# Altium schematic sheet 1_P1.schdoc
size 431 x 309 mm; Symbol: Sheet-Symbol_A4; Device: Sheet-Symbol_A4; @Page Name: P1; @Create Date: 2023-03-24; @Page Count: 1; @Page No: 1; @Project Name: weather_clock; @Schematic Name: Schematic1; @Update Date: 2023-03-27; Company: 嘉立创EDA; Page Size: A4; Version: V1.0
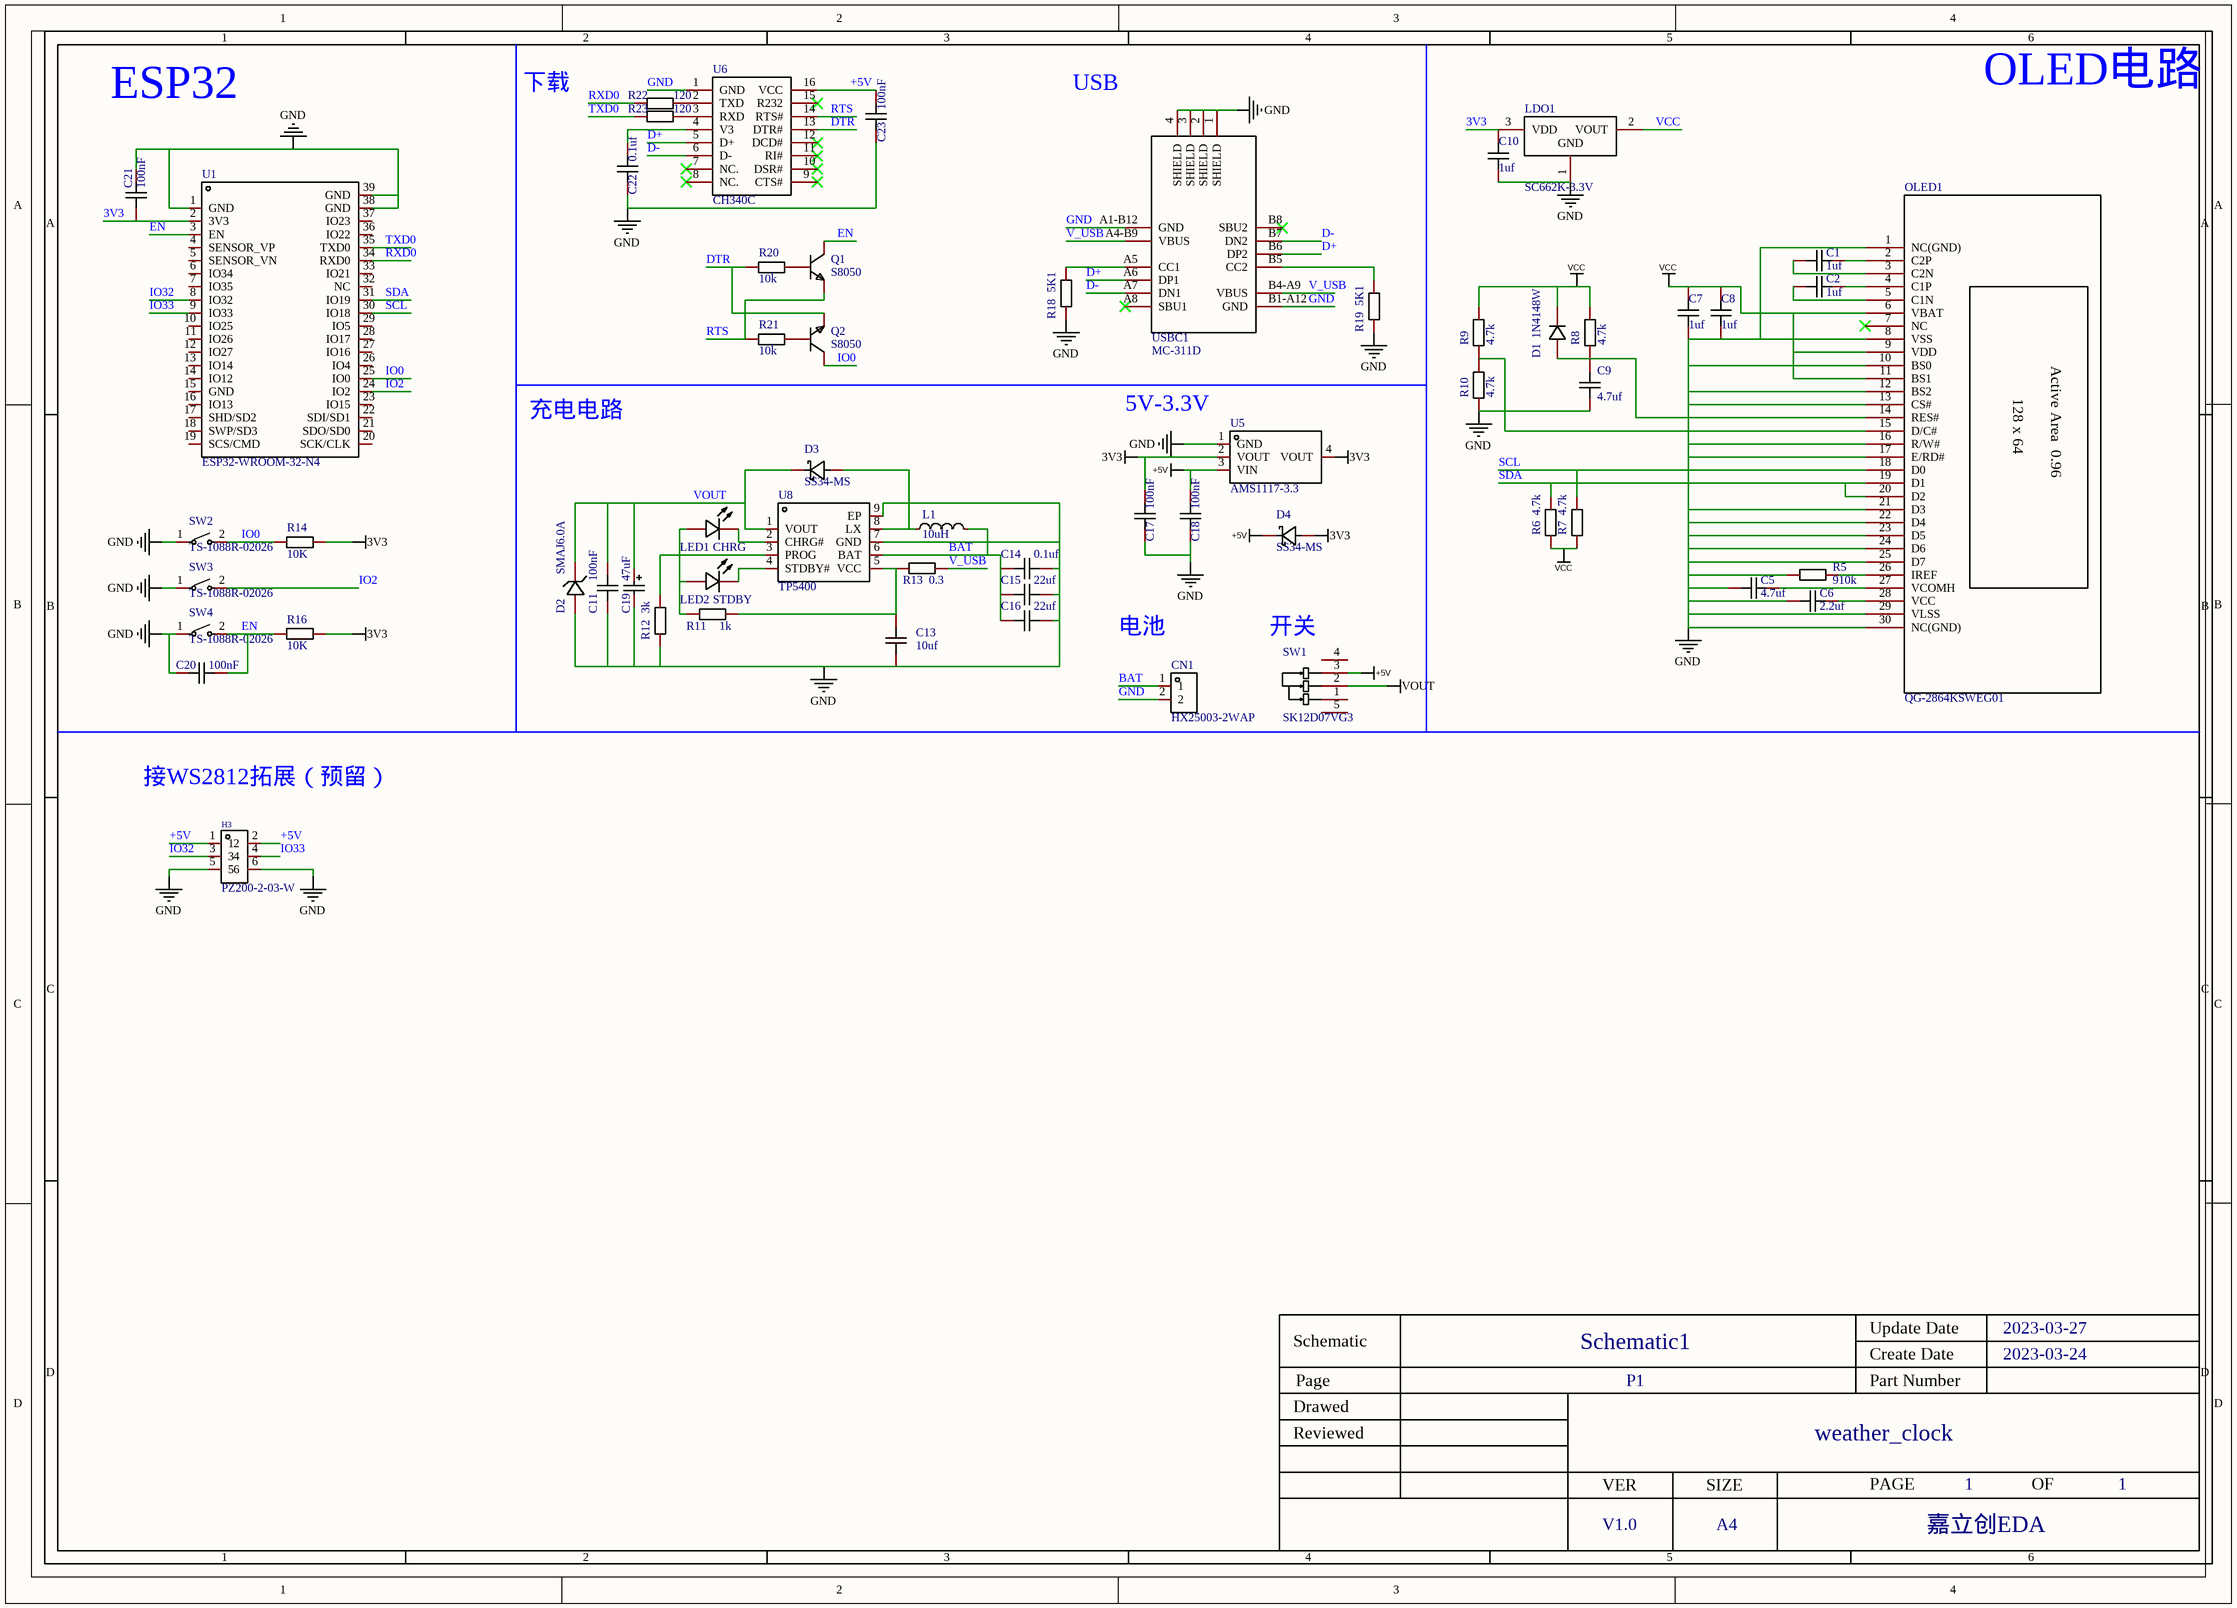
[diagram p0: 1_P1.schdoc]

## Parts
C1  1uf  [C0603]
C2  1uf  [C0603]
C5  4.7uf  [C0603]
C6  2.2uf  [C0603]
C7  1uf  [C0603]
C8  1uf  [C0603]
C9  4.7uf  [C0603]
C10  1uf  [C0603]
C11  100nF  [C0603]
C13  10uf  [C0603]
C14  0.1uf  [C0603]
C15  22uf  [C0603]
C16  22uf  [C0603]
C17  100nF  [C0603]
C18  100nF  [C0603]
C19  47uF  [CASE-A_3216]
C20  100nF  [C0603]
C21  100nF  [C0603]
C22  0.1uf  [C0603]
C23  100nF  [C0603]
CN1  HX25003-2WAP  [CONN-TH_2P-P2.50_HX25003-2WAP]
D1  1N4148W  [SOD-123_L2.8-W1.8-LS3.7-RD]
D2  SMAJ6.0A  [SMA_L4.3-W2.6-LS5.2-RD]
D3  SS34-MS  [DO-214AC_L4.3-W2.7-LS5.0-RD]
D4  SS34-MS  [DO-214AC_L4.3-W2.7-LS5.0-RD]
H3  PZ200-2-03-W  [HDR-TH_6P-P2.00-H-M-R2-C3-S2.00-W9.8]
L1  10uH  [IND-SMD_L4.5-W4.1_TMPA0402SP]
LDO1  SC662K-3.3V  [SOT-23-3_L2.9-W1.3-P1.90-LS2.4-BR]
LED1  CHRG  [LED0603-R-RD_GREEN]
LED2  STDBY  [LED0603-R-RD_GREEN]
OLED1  QG-2864KSWEG01  [OLED-SMD_QG-2864KSWEG01]
Q1  S8050  [SOT-23-3_L2.9-W1.6-P1.90-LS2.8-BR]
Q2  S8050  [SOT-23-3_L2.9-W1.6-P1.90-LS2.8-BR]
R5  910k  [R0603]
R6  4.7k  [R0603]
R7  4.7k  [R0603]
R8  4.7k  [R0603]
R9  4.7k  [R0603]
R10  4.7k  [R0603]
R11  1k  [R0603]
R12  3k  [R0603]
R13  0.3  [R0603]
R14  10K  [R0603]
R16  10K  [R0603]
R18  5K1  [R0603]
R19  5K1  [R0603]
R20  10k  [R0603]
R21  10k  [R0603]
R22  120  [R0603]
R23  120  [R0603]
SW1  SK12D07VG3  [SW-TH_SK12D07VG3]
SW2  TS-1088R-02026  [SW-SMD_L3.9-W3.0-P4.45]
SW3  TS-1088R-02026  [SW-SMD_L3.9-W3.0-P4.45]
SW4  TS-1088R-02026  [SW-SMD_L3.9-W3.0-P4.45]
U1  ESP32-WROOM-32-N4  [WIFIM-SMD_ESP32-WROOM-32-N4]
U5  AMS1117-3.3  [SOT-223-3_L6.5-W3.4-P2.30-LS7.0-BR]
U6  CH340C  [SOP-16_L10.0-W3.9-P1.27-LS6.0-BL]
U8  TP5400  [ESOP-8_L4.9-W3.9-P1.27-LS6.0-BL-EP]
USBC1  MC-311D  [USB-C-SMD_MC-311D]

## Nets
3V3: C10.1 C17.2 C21.1 D4.2(K) LDO1.3(VDD) R14.2 R16.2 U1.2(3V3) U5.2(VOUT) U5.4(VOUT)
+5V: C18.2 C23.2 D4.1(A) H3.1 H3.2 SW1.3 U5.3(VIN) U6.16(VCC)
GND: C5.2 C6.2 C7.2 C8.2 C9.2 C10.2 C11.1 C13.1 C14.2 C15.2 C16.2 C17.1 C18.1 C19.2 C20.1 C21.2 C22.2 C23.1 CN1.2 D2.2(A) H3.5 H3.6 LDO1.1(GND) OLED1.1(NC(GND)) OLED1.8(VSS) OLED1.10(BS0) OLED1.12(BS2) OLED1.13(CS#) OLED1.16(R/W#) OLED1.17(E/RD#) OLED1.21(D3) OLED1.22(D4) OLED1.23(D5) OLED1.24(D6) OLED1.25(D7) OLED1.29(VLSS) OLED1.30(NC(GND)) R5.1 R10.1 R12.1 R18.1 R19.1 SW2.1 SW3.1 SW4.1 U1.1(GND) U1.38(GND) U1.39(GND) U5.1(GND) U6.1(GND) U8.7(GND) U8.9(EP) USBC1.1(SHIELD) USBC1.2(SHIELD) USBC1.3(SHIELD) USBC1.4(SHIELD) USBC1.A1-B12(GND) USBC1.B1-A12(GND)
VCC: C7.1 C8.1 D1.1(K) LDO1.2(VOUT) OLED1.6(VBAT) OLED1.9(VDD) OLED1.11(BS1) R6.1 R7.1 R8.2 R9.2
VOUT: C11.2 C19.1 D2.1(C) D3.1(A) SW1.2 U8.1(VOUT)
BAT: C14.1 C15.1 C16.1 CN1.1 L1.2 U8.6(BAT)
D+: U6.5(D+) USBC1.A6(DP1) USBC1.B6(DP2)
D-: U6.6(D-) USBC1.A7(DN1) USBC1.B7(DN2)
DTR: Q2.2 R20.1 U6.13(DTR#)
EN: C20.2 Q1.3 R16.1 SW4.2 U1.3(EN)
IO0: Q2.3 R14.1 SW2.2 U1.25(IO0)
IO2: SW3.2 U1.24(IO2)
IO32: H3.3 U1.8(IO32)
IO33: H3.4 U1.9(IO33)
RTS: Q1.2 R21.1 U6.14(RTS#)
RXD0: R22.1 U1.34(RXD0)
SCL: OLED1.18(D0) R7.2 U1.30(IO18)
SDA: OLED1.19(D1) OLED1.20(D2) R6.2 U1.31(IO19)
TXD0: R23.1 U1.35(TXD0)
V_USB: R13.2 USBC1.A4-B9(VBUS) USBC1.B4-A9(VBUS)
NetC1_1: C1.1 OLED1.2(C2P)
NetC1_2: C1.2 OLED1.3(C2N)
NetC2_1: C2.1 OLED1.4(C1P)
NetC2_2: C2.2 OLED1.5(C1N)
NetC5_1: C5.1 OLED1.27(VCOMH)
NetC6_1: C6.1 OLED1.28(VCC)
NetC9_1: C9.1 D1.2(A) OLED1.14(RES#) R8.1
NetC13_2: C13.2 R11.2 R13.1 U8.5(VCC)
NetC22_1: C22.1 U6.4(V3)
NetD3_2: D3.2(K) L1.1 U8.8(LX)
NetLED1_1: LED1.1(A) LED2.1(A) R11.1
NetLED1_2: LED1.2(K) U8.2(CHRG#)
NetLED2_2: LED2.2(K) U8.4(STDBY#)
NetOLED1_15: OLED1.15(D/C#) R9.1 R10.2
NetOLED1_26: OLED1.26(IREF) R5.2
NetQ1_1: Q1.1 R20.2
NetQ2_1: Q2.1 R21.2
NetR12_2: R12.2 U8.3(PROG)
NetR18_2: R18.2 USBC1.A5(CC1)
NetR19_2: R19.2 USBC1.B5(CC2)
NetR22_2: R22.2 U6.2(TXD)
NetR23_2: R23.2 U6.3(RXD)

Not connected (* = marked no-connect by the designer): OLED1 7(NC)*; SW1 1 4 5; U1 4(SENSOR_VP) 5(SENSOR_VN) 6(IO34) 7(IO35) 10(IO25) 11(IO26) 12(IO27) 13(IO14) 14(IO12) 15(GND) 16(IO13) 17(SHD/SD2) 18(SWP/SD3) 19(SCS/CMD) 20(SCK/CLK) 21(SDO/SD0) 22(SDI/SD1) 23(IO15) 26(IO4) 27(IO16) 28(IO17) 29(IO5) 32(NC) 33(IO21) 36(IO22) 37(IO23); U6 7(NC.)* 8(NC.)* 9(CTS#)* 10(DSR#)* 11(RI#)* 12(DCD#)* 15(R232)*; USBC1 A8(SBU1)* B8(SBU2)*

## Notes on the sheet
- ESP32
- 下载
- USB
- OLED电路
- 充电电路
- (near U5) 5V-3.3V
- 电池
- (near SW1) 开关
- 接WS2812拓展（预留）

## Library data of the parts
C1 C5-C10 C13-C16 C22 = CAP_0603: Symbol: CapAcitance; Convert to PCB: yes; Value: 100nF
C2 C11 C17 C18 C20 C21 C23 = CAP_0603: Symbol: CapAcitance; Convert to PCB: yes
C19 = TC212A476K010Y: 容值:47uF;精度:±10%;额定电压:10V;等效串联电阻:1.5Ω@100kHz;工作温度:-55℃~+125℃;; Manufacturer: Sunlord(顺络); Add into BOM: yes; Tolerance: ±10%; Rated Voltage: 10V
CN1 = HX25003-2WAP: 参考系列:XH;间距:2.5mm;插针结构:1x2P;排数:1;每排PIN数:2;行距:-;公母:公型插针;安装方式:弯插;额定电流:-;工作温度范围:-;; Manufacturer: HX(红星); Add into BOM: yes; Reference Series: XH; Pitch: 2.5mm; Pins Structure: 1x2P; Number of PINs Per Row: 2; Gender: 公型插针
D1 = 1N4148W_C2099: 二极管配置:独立式;功率:500mW;直流反向耐压(Vr):100V;平均整流电流(Io):150mA;正向压降(Vf):1.25V@150mA;反向电流(Ir):1uA@75V;反向恢复时间(trr):4ns;工作温度:+150℃@(Tj);; Manufacturer: CJ(江苏长电/长晶); Symbol: 1N4148W T4; Add into BOM: yes; Diode Configuration: 独立式; Power Dissipation: 500mW; Reverse Voltage (Vr): 100V; Average Rectified Current (Io): 150mA; Reverse Recovery Time (trr): 4ns
D2 = SMAJ6.0A_C223993: 极性:单向;反向截止电压(Vrwm):6V;击穿电压:6.67V;峰值脉冲电流(Ipp)@10/1000μs:-;最大钳位电压:10.3V;峰值脉冲功率(Ppp)@10/1000μs:400W;; Manufacturer: Littelfuse(美国力特); Add into BOM: yes; Polarity: 单向; Reverse Stand-Off Voltage (Vrwm): 6V; Breakdown Voltage: 6.67V; Maximum Clamping Voltage: 10.3V; Peak Pulse Power Dissipation (Ppp)@10/1000μs: 400W
D3 D4 = SS34-MS: 二极管配置:-;直流反向耐压(Vr):40V;平均整流电流(Io):3A;正向压降(Vf):550mV@3A;反向电流(Ir):500uA@40V;; Manufacturer: MSKSEMI(美森科); Add into BOM: yes; Reverse Voltage (Vr): 40V; Average Rectified Current (Io): 3A
H3 = PZ200-2-03-W: 间距:2mm;总PIN位数:6;排数:2;插针结构:2x3P;行距:2mm;安装类型:弯插;圆针/方针:方针;额定电流:1.5A;额定电压:-;配合针长度:4mm;塑高:2mm;端接针长度:-;工作温度范围:-40℃~+105℃;颜色:黑色;; Manufacturer: HCTL(华灿天禄); Add into BOM: yes; Pitch: 2mm; Pin Structure: 2x3P; Circluar Pins/Square Pins: 方针; Current Rating (Max): 1.5A
L1 = TMPC0402HP-100MG-Z02: 电感值:10uH;精度:±20%;额定电流:1.4A;直流电阻(DCR):215mΩ;; Manufacturer: TAI-TECH(台庆); Add into BOM: yes; Tolerance: ±20%; Rated Current: 1.4A; DC Resistance (DCR): 215mΩ
LDO1 = SC662K-3.3V: 输出类型:固定;输出极性:正;最大输入电压:6V;输出电压:3.3V;输出电流:250mA;电源纹波抑制比(PSRR):50dB@(1kHz);; Manufacturer: FM(富满); Add into BOM: yes; Output Type: 固定; Output Polarity: 正; Number of Outputs: 1; Maximum Input Voltage: 6V; Output Voltage: 3.3V; Dropout Voltage: 38mV@(10mA); Output Current: 250mA
LED1 LED2 = TLMG1100-GS08: 照明颜色:普绿/黄绿;色温 - CCT（K）:-;主波长/色坐标:570nm;; Manufacturer: VISHAY(威世); Add into BOM: yes; Illumination Color: 普绿/黄绿; Luminous Intensity (IF=20mA): 35mcd; Dominant Wavelength / Coordinate rank: 570nm
OLED1 = QG-2864KSWEG01: OLED屏幕 黑底白字; Manufacturer: Allvision(全智景); Add into BOM: yes
Q1 Q2 = S8050_C105433: 晶体管类型:NPN;集射极击穿电压(Vceo):25V;集电极电流(Ic):500mA;功率(Pd):300mW;直流电流增益(hFE@Ic,Vce):120@50mA,1V;; Manufacturer: CJ(江苏长电/长晶); Add into BOM: yes; Transistor Type: NPN; Collector-Emitter Breakdown Voltage (Vceo): 25V; Collector Current (Ic): 500mA; Power Dissipation (Pd): 300mW; Collector Cut-Off Current (Icbo): 100nA; Collector-Emitter Saturation Voltage (VCE(sat)@Ic,Ib): 600mV@500mA,50mA; Transition Frequency (fT): 150MHz
R5-R13 R18 R19 R22 R23 = Res_0603: Symbol: 电阻; Convert to PCB: yes; Value: 10K
R14 R16 R20 R21 = Res_0603: Symbol: 电阻; Convert to PCB: yes
SW1 = SK12D07VG3: Manufacturer: SHOU HAN(首韩); Symbol: SK12D07VG3_C431547; Add into BOM: yes
SW2-SW4 = TS-1088R-02026: 触点电流:50mA;额定电压(DC):12V;电路结构:单刀单掷;安装方式:立贴;按钮形状:圆形按钮;带灯:-;开关长度:3.9mm;开关宽度:2.93mm;开关高度:2mm;; Manufacturer: XUNPU(讯普); Add into BOM: yes; Contact Current: 50mA; Voltage Rating (DC): 12V; Circuit: 单刀单掷; Actuator Style: 圆形按钮; Switch Length: 3.9mm; Switch Width: 2.93mm; Switch Height: 2mm
U1 = ESP32-WROOM-32-N4: WiFi+蓝牙4.2+双核CPU,ESP32; Manufacturer: ESPRESSIF(乐鑫); Add into BOM: yes
U5 = AMS1117-3.3_C6186: 输出类型:固定;输出极性:正;输出通道数:1;最大输入电压:-;输出电压:3.3V;压差:1.3V@(800mA);静态电流(地电流):-;输出电流:1A;电源纹波抑制比(PSRR):72dB@(120Hz);噪声:-;特性:-;工作温度:-;; Manufacturer: AMS; Add into BOM: yes; Output Type: 固定; Output Polarity: 正; Number of Outputs: 1; Output Voltage: 3.3V; Output Current: 1A
U6 = CH340C: 应用功能:Transceiver;接口协议:USB 2.0;数据速率:2Mbps;供电电压:3.3V；5V;; Manufacturer: WCH(南京沁恒); Add into BOM: yes; Protocol: USB 2.0; Data Rate: 2Mbps
U8 = TP5400: Manufacturer: TOPPOWER(南京拓微); Symbol: TP5400_C2891434; Add into BOM: yes
USBC1 = MC-311D: 连接器类型:Type-C;标准:-;公母:母座;触点数量:12;端口数量:1;; Manufacturer: SOFNG(硕方); Add into BOM: yes; Connector Type: Type-C; Gender: 母座; Number of Contacts: 12; Number of Ports: 1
